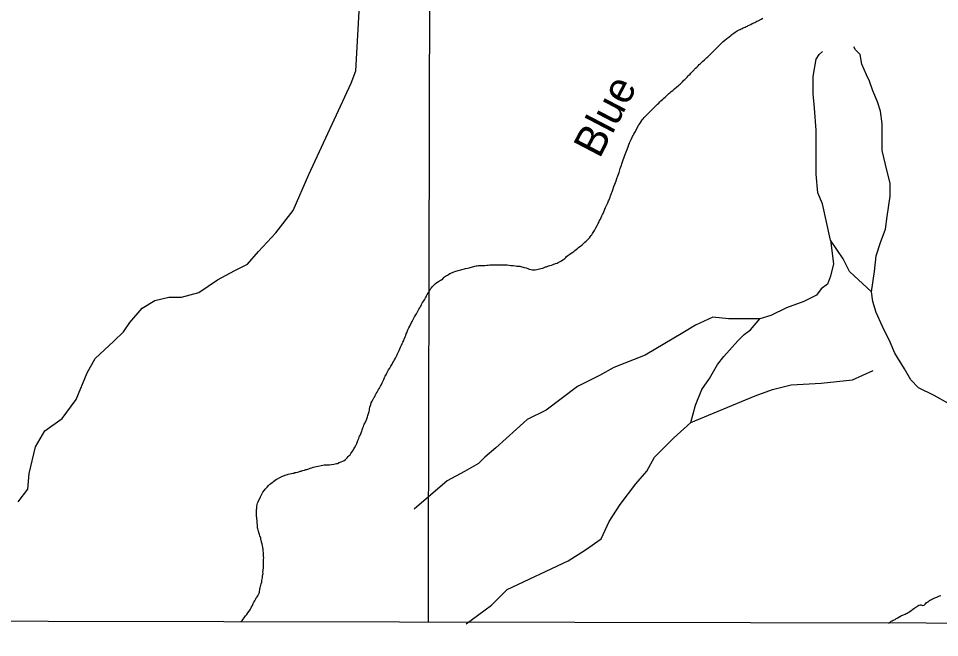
# Model space of a CAD drawing. Extents: x 3192927 to 3230760, y 831141 to 856475.
# Drawn here: x 3201003 to 3203997, y 836487 to 838498 of the extents above; entities that cross this region are included whole.
import ezdxf

# ---------------------------------------------------------------- set-up
doc = ezdxf.new("R2010")
doc.units = 0
for name, color, linetype in [('V-GRID-FRAM', 7, 'Continuous'), ('V-GRID-MAJR', 7, 'Continuous'), ('V-RIVR-IDEN', 7, 'Continuous'), ('V-TOPO-SHOR', 7, 'Continuous')]:
    doc.layers.add(name, color=color, linetype=linetype)

msp = doc.modelspace()

# ---------------------------------------------------------------- linework, layer by layer
at = {"layer": 'V-GRID-FRAM'}
msp.add_lwpolyline([(3197144.3, 854733.3), (3228527.7, 854674), (3228501.2, 836486.7), (3197102, 836546.1), (3197144.3, 854733.3)], dxfattribs=at)
at = {"layer": 'V-GRID-MAJR'}
msp.add_spline([(3202335.2, 836536.2), (3202348.4, 842596.7), (3202361.7, 848659.1), (3202374.9, 854721.5), (3202374.9, 854723.4)], degree=3, dxfattribs=at)
at = {"layer": 'V-TOPO-SHOR'}
for points in [[(3201002.3, 836928.1), (3201032.9, 836969), (3201038, 837020), (3201058.3, 837106.9), (3201088.9, 837158), (3201145.1, 837198.9), (3201191, 837260.2), (3201226.7, 837347.1), (3201252.2, 837393), (3201313.4, 837449.3), (3201344, 837479.9), (3201364.4, 837510.6), (3201405.3, 837556.6), (3201446.1, 837582.2), (3201492.1, 837592.4), (3201532.9, 837592.5), (3201589.1, 837607.8), (3201650.3, 837648.7), (3201706.5, 837679.4), (3201747.3, 837699.9), (3201783, 837740.8), (3201839.2, 837802.1), (3201895.3, 837873.7), (3201946.3, 837991.2), (3202083.9, 838287.5), (3202099.2, 838328.4), (3202139.5, 839043.4)], [(3203135.6, 838269.3), (3203143.1, 838275.5), (3203147.1, 838279.5), (3203150.2, 838282.1), (3203153.1, 838284.7), (3203158.4, 838289.3), (3203161.2, 838292.1), (3203165.8, 838297.4), (3203168.7, 838300), (3203175.9, 838307.8), (3203179.2, 838311.2), (3203181.6, 838313.5), (3203185.7, 838317.6), (3203188.3, 838320.2), (3203194.3, 838326.4), (3203203.9, 838336.4), (3203207.5, 838340), (3203212.3, 838344.7), (3203215.6, 838348.3), (3203218.7, 838351.1), (3203225.7, 838357.8), (3203232.6, 838364), (3203236, 838366.8), (3203240.5, 838371.1), (3203243.4, 838373.8), (3203247.5, 838377.8), (3203252.5, 838382.6), (3203258.5, 838388.7), (3203262.1, 838392.3), (3203266.4, 838396.4), (3203268.5, 838398.7), (3203271.7, 838401.8), (3203279.6, 838409.2), (3203285.1, 838414.9), (3203287.9, 838418), (3203293.4, 838423), (3203297.3, 838426.6), (3203305.7, 838433.2), (3203311.4, 838437.8), (3203318.8, 838443.5), (3203321.2, 838445.6), (3203327.9, 838450.1), (3203332.2, 838453.7), (3203338.9, 838457.5), (3203345.6, 838461.1), (3203348.7, 838462.5), (3203352.1, 838464.1), (3203355.2, 838465.6), (3203358.8, 838467.5), (3203364.3, 838469.8), (3203367.8, 838471.7), (3203371.9, 838473.4), (3203375, 838474.8), (3203380.3, 838477.2), (3203383.6, 838478.8), (3203387.9, 838481.2), (3203395.8, 838484.8), (3203399.9, 838487.2), (3203403.2, 838488.8), (3203406.8, 838490.7), (3203416.4, 838495.7), (3203422.1, 838498.8)], [(3204025.5, 837247.2), (3203979.5, 837272.7), (3203928.4, 837298.2), (3203902.9, 837323.7), (3203882.4, 837359.5), (3203851.7, 837410.5), (3203836.4, 837446.2), (3203810.8, 837497.3), (3203790.3, 837543.2), (3203780.1, 837579), (3203775, 837609.6), (3203785.1, 837676), (3203790.2, 837727.1), (3203805.5, 837773.1), (3203820.8, 837813.9), (3203825.8, 837854.8), (3203836, 837921.2), (3203836, 837962.1), (3203820.6, 838023.3), (3203810.3, 838069.3), (3203810.3, 838120.4), (3203810.3, 838156.1), (3203805.1, 838197), (3203794.9, 838227.6), (3203779.5, 838263.3), (3203769.3, 838294), (3203759.1, 838314.4), (3203743.7, 838350.1), (3203738.6, 838380.8), (3203723.2, 838396.1), (3203718.1, 838406.3)], [(3203775, 837609.6), (3203703.4, 837676), (3203682.9, 837716.8), (3203662.5, 837747.4), (3203642, 837778), (3203616.4, 837895.5), (3203601, 837931.2), (3203595.9, 837992.5), (3203595.8, 838079.3), (3203595.8, 838135.5), (3203590.6, 838207), (3203585.5, 838253), (3203585.4, 838309.2), (3203595.6, 838365.3), (3203605.8, 838380.7), (3203616, 838390.9)], [(3202834.7, 837762.9), (3202837.1, 837764.8), (3202840.6, 837768.3), (3202843.3, 837771), (3202848.1, 837775), (3202852.4, 837779), (3202855, 837781.2), (3202858.8, 837785.5), (3202861, 837788.3), (3202864.4, 837792.6), (3202866, 837795.5), (3202868.2, 837799.3), (3202874.9, 837809.5), (3202877.3, 837813.6), (3202880, 837817.6), (3202883.6, 837825), (3202885.2, 837828.1), (3202886.7, 837831.7), (3202889.8, 837837.4), (3202891.5, 837841.2), (3202894.1, 837846.2), (3202897, 837851.7), (3202899.4, 837856.7), (3202901.3, 837861), (3202903, 837864.1), (3202905.2, 837869.8), (3202911.4, 837883.4), (3202914.1, 837890.1), (3202916, 837894.4), (3202918.7, 837899.6), (3202920.8, 837905.1), (3202922.3, 837908.9), (3202925.6, 837918), (3202926.8, 837921.3), (3202929, 837926.8), (3202930.9, 837930.6), (3202932.1, 837934.7), (3202934.3, 837940.9), (3202938.2, 837952.3), (3202940.8, 837960), (3202943, 837965.2), (3202945.1, 837970.2), (3202948, 837978.3), (3202951.2, 837986.9), (3202953.1, 837992.7), (3202955.2, 837997.9), (3202956.2, 838001.5), (3202957.7, 838006.5), (3202958.9, 838010.1), (3202962.7, 838021.5), (3202963.9, 838025.6), (3202966.3, 838032), (3202968.7, 838038.9), (3202970.4, 838043.7), (3202972.8, 838050.8), (3202977.9, 838064.4), (3202980.8, 838072.5), (3202982.2, 838076.1), (3202984.2, 838081.1), (3202986.8, 838088.8), (3202988.5, 838092.3), (3202990.4, 838096.6), (3202991.9, 838100.2), (3202994.5, 838105), (3202999.1, 838114.3), (3203001, 838118.1), (3203003.1, 838121.7), (3203006.3, 838127.4), (3203007.9, 838131.2), (3203011.8, 838138.1), (3203016.1, 838146.2), (3203018.5, 838151), (3203020.4, 838154.1), (3203023.3, 838158.4), (3203026.4, 838163.1), (3203030.5, 838168.6), (3203033.6, 838172.2), (3203037, 838176.2), (3203039.4, 838179.1), (3203042.2, 838181.9), (3203049.7, 838189.8), (3203052.5, 838192.4), (3203056.6, 838196.5), (3203059, 838198.8), (3203062.4, 838202.2), (3203064.8, 838204.6), (3203071.7, 838211), (3203076.3, 838216), (3203079.8, 838219.6), (3203083.7, 838223.4), (3203087.5, 838227.2), (3203091.1, 838230.5), (3203096.8, 838236), (3203100.7, 838239.3), (3203104.5, 838242.9), (3203109.8, 838247.6), (3203117, 838254.1), (3203119.8, 838256.7), (3203124.6, 838260.7), (3203129.6, 838264.5), (3203135.6, 838269.3)], [(3203642, 837778), (3203652.3, 837701.4), (3203642.1, 837660.6), (3203631.9, 837635), (3203611.5, 837619.7), (3203596.2, 837599.3), (3203555.4, 837578.8), (3203499.2, 837558.3), (3203448.2, 837532.7), (3203412.4, 837522.5), (3203366.5, 837522.5), (3203310.3, 837522.4), (3203259.2, 837527.5), (3203203, 837501.9), (3203162.2, 837476.3), (3203039.7, 837404.7), (3202937.6, 837363.8), (3202891.6, 837338.2), (3202820.2, 837302.4), (3202718.1, 837225.7), (3202656.8, 837195), (3202621.1, 837164.3), (3202554.8, 837103), (3202519, 837072.3), (3202498.6, 837051.9), (3202452.7, 837026.3), (3202396.5, 836995.6), (3202289.3, 836903.6)], [(3202352.2, 837630.9), (3202356.3, 837634.5), (3202358.7, 837636.6), (3202362.8, 837639.9), (3202368.5, 837643.5), (3202371.1, 837645.2), (3202374.5, 837647.5), (3202377.6, 837649.4), (3202382.4, 837652.3), (3202385.2, 837656.1), (3202387.6, 837658.5), (3202390.7, 837660.6), (3202397.2, 837664.4), (3202400.3, 837666.3), (3202405.1, 837669.2), (3202413.2, 837672.5), (3202416.3, 837673.7), (3202421.1, 837675.6), (3202424.5, 837676.8), (3202429.2, 837678.4), (3202432.1, 837679.4), (3202436.6, 837680.3), (3202440.7, 837681.2), (3202443.8, 837682), (3202448.4, 837683.4), (3202452.7, 837684.8), (3202455.8, 837685.5), (3202463.2, 837686.9), (3202468.2, 837688.1), (3202471.1, 837689), (3202475.8, 837690.2), (3202486.1, 837692.8), (3202490.2, 837694.2), (3202494.2, 837694.9), (3202498.3, 837695.1), (3202503.5, 837695.6), (3202508.8, 837695.6), (3202516, 837696), (3202519.1, 837695.6), (3202524.8, 837696.5), (3202529.1, 837697), (3202534.8, 837697.7), (3202541.3, 837697.6), (3202544.4, 837697.9), (3202549.6, 837697.6), (3202559.2, 837697.8), (3202567.5, 837698), (3202574, 837697.8), (3202582.3, 837698), (3202591.2, 837697.5), (3202597.9, 837696.8), (3202603.3, 837695.8), (3202610.7, 837695), (3202618.1, 837694.3), (3202622.2, 837693.8), (3202629.1, 837693.1), (3202632.5, 837692.8), (3202638.9, 837691.4), (3202643.7, 837690.4), (3202647, 837689.4), (3202653.2, 837687.5), (3202658.5, 837685.6), (3202663, 837683.9), (3202669.4, 837682.2), (3202673.5, 837681.7), (3202677.1, 837681.5), (3202682.6, 837681.9), (3202687.3, 837682.9), (3202691.6, 837684), (3202696.4, 837684.5), (3202700.2, 837685.5), (3202706.7, 837687.3), (3202709.6, 837688.3), (3202715.5, 837690.7), (3202718.6, 837691.6), (3202723, 837693), (3202730.4, 837695.4), (3202735.1, 837696.3), (3202740.6, 837698.5), (3202748.8, 837701.8), (3202753.3, 837703.2), (3202756.9, 837704.9), (3202763.8, 837708.2), (3202767.6, 837710.3), (3202772.2, 837713.4), (3202775.8, 837716.3), (3202778.2, 837718.4), (3202781.5, 837722), (3202783.9, 837724.3), (3202788, 837727.7), (3202792.1, 837730.3), (3202794.5, 837732.2), (3202799.7, 837735.8), (3202804.3, 837738.8), (3202807.6, 837741), (3202811.7, 837744.3), (3202815.8, 837747.4), (3202821, 837752.2), (3202824.6, 837754.8), (3202830.1, 837758.8), (3202834.7, 837762.9)], [(3202118.7, 837157), (3202120.4, 837162), (3202122.1, 837167.7), (3202124.2, 837172.7), (3202125.7, 837176.5), (3202126.9, 837180.4), (3202129.3, 837184.9), (3202132.6, 837192), (3202134.8, 837197.1), (3202137, 837203.5), (3202138.7, 837207.8), (3202141.1, 837214.5), (3202142.5, 837220.9), (3202143.7, 837225.9), (3202144.2, 837229.3), (3202145.4, 837235), (3202147.8, 837244), (3202149.8, 837248.8), (3202152.6, 837254.3), (3202154.8, 837258.6), (3202158.2, 837265.3), (3202159.8, 837268.1), (3202162.3, 837272.7), (3202165.9, 837279.6), (3202168.5, 837284.3), (3202173.5, 837292.2), (3202176.2, 837296.7), (3202177.9, 837299.6), (3202180, 837303.4), (3202181.5, 837306.3), (3202185.3, 837314.4), (3202187.2, 837318.2), (3202189.1, 837322.7), (3202190.6, 837325.6), (3202193, 837332), (3202195.2, 837335.8), (3202199, 837342.7), (3202200.4, 837346.1), (3202202.4, 837349.6), (3202206, 837356.1), (3202209.8, 837362.5), (3202213.2, 837368), (3202215.6, 837372), (3202217.2, 837375.1), (3202220.1, 837379.9), (3202222.5, 837384.4), (3202225.4, 837389.2), (3202228.5, 837394.7), (3202231.4, 837400.9), (3202233.6, 837405.4), (3202234.8, 837408.8), (3202236.7, 837413.3), (3202239.8, 837419.7), (3202242.5, 837425), (3202244.4, 837429.7), (3202245.8, 837432.8), (3202248, 837437.1), (3202250.4, 837442.1), (3202252.6, 837446.9), (3202255, 837452.1), (3202256.2, 837456.2), (3202259.3, 837463.3), (3202261.5, 837468.4), (3202263.4, 837473.4), (3202264.8, 837476.7), (3202267.5, 837483.4), (3202268.9, 837486.2), (3202270.6, 837490.3), (3202272, 837493.2), (3202274.9, 837498.6), (3202280.7, 837510.1), (3202282.9, 837513.9), (3202284.5, 837517.7), (3202287.2, 837522.5), (3202290.3, 837528.4), (3202292.5, 837532.2), (3202294.1, 837534.9), (3202296.1, 837538.7), (3202299.4, 837544.9), (3202304.5, 837553.5), (3202307.1, 837557.7), (3202308.8, 837561.1), (3202310.5, 837563.9), (3202312.9, 837568.5), (3202314.3, 837571.3), (3202316.2, 837574.9), (3202320.1, 837580.6), (3202322.2, 837584.4), (3202325.6, 837590.2), (3202327.8, 837594.2), (3202329.2, 837597.1), (3202331.6, 837601.6), (3202334.2, 837605.4), (3202336.4, 837609), (3202337.8, 837611.8), (3202340.7, 837616.1), (3202343.1, 837620.7), (3202345, 837623.3), (3202347.2, 837625.7), (3202349.8, 837628.5), (3202352.2, 837630.9)], [(3202458.2, 836530.9), (3202539.9, 836592.3), (3202590.9, 836643.4), (3202790, 836735.5), (3202846.1, 836771.3), (3202897.2, 836807.1), (3202922.7, 836863.3), (3202958.4, 836919.5), (3203009.4, 836985.9), (3203045.1, 837026.8), (3203070.6, 837072.8), (3203131.8, 837134.1), (3203188, 837185.2), (3203203.3, 837241.4), (3203223.6, 837292.5), (3203249.1, 837328.3), (3203274.6, 837374.3), (3203295.1, 837399.8), (3203341, 837450.9), (3203361.4, 837471.4), (3203381.8, 837486.7), (3203412.4, 837522.5)], [(3203188, 837185.2), (3203397.3, 837272.2), (3203453.5, 837292.7), (3203514.7, 837308.1), (3203611.8, 837313.3), (3203713.9, 837323.6), (3203780.3, 837354.3)], [(3201780.1, 836843.4), (3201779.4, 836853.2), (3201779, 836858.7), (3201778.7, 836862.7), (3201778.3, 836867.2), (3201777.6, 836872), (3201777.4, 836877.3), (3201776.9, 836880.4), (3201776.7, 836888.5), (3201776.7, 836893.3), (3201776.9, 836899.2), (3201777, 836902.6), (3201777.4, 836905.9), (3201778.2, 836912.6), (3201778.9, 836919.3), (3201779.9, 836923.8), (3201781.6, 836928.1), (3201783.5, 836931.5), (3201787.1, 836938.6), (3201789.3, 836943.6), (3201792.4, 836950.3), (3201794.5, 836954.3), (3201797.4, 836959.1), (3201802.2, 836965.3), (3201805.1, 836968.6), (3201808, 836972), (3201811.3, 836975.8), (3201815.9, 836980.8), (3201819.5, 836984.8), (3201822.8, 836987.4), (3201827.1, 836990.5), (3201830.7, 836992.7), (3201833.1, 836994.8), (3201837.4, 836997.7), (3201841.2, 837001), (3201845.3, 837002.9), (3201852, 837006.5), (3201855.4, 837008.3), (3201858.2, 837009.5), (3201864, 837011.7), (3201867.1, 837012.9), (3201870.2, 837014), (3201873.5, 837015.5), (3201876.9, 837016.6), (3201880, 837017.3), (3201884.5, 837018.5), (3201890.2, 837019.9), (3201894.8, 837021.1), (3201897.9, 837021.3), (3201901.5, 837022.5), (3201906, 837023.5), (3201913.9, 837025.6), (3201918, 837027), (3201921.3, 837027.7), (3201926.3, 837029.4), (3201932.1, 837031), (3201936.8, 837032.4), (3201939.9, 837033.2), (3201946.4, 837035.3), (3201950.9, 837036.7), (3201956, 837038.4), (3201960.7, 837039.8), (3201966.5, 837041.2), (3201971, 837042.1), (3201976.5, 837043.3), (3201986.8, 837045.9), (3201992, 837046.8), (3201996.8, 837047.5), (3202003, 837048.2), (3202006.4, 837048.2), (3202013.8, 837048.2), (3202020, 837049.1), (3202028.3, 837050.1), (3202032.2, 837051), (3202036.5, 837052.2), (3202039.8, 837052.7), (3202045.8, 837055), (3202051.5, 837057.4), (3202057.5, 837060), (3202061.8, 837062.4), (3202065.6, 837064.8), (3202068.3, 837066.9), (3202071.1, 837070.5), (3202074.5, 837074.5), (3202078.1, 837078.6), (3202080.7, 837080.9), (3202083.6, 837084.5), (3202089.1, 837092.6), (3202091.5, 837096.9), (3202093.2, 837100), (3202094.9, 837102.9), (3202099.4, 837111), (3202102.3, 837117.4), (3202105, 837124.1), (3202106.2, 837126.9), (3202109.1, 837133.9), (3202110.5, 837137.9), (3202111.7, 837140.8), (3202114.1, 837145.5), (3202116.5, 837151.7), (3202118.7, 837157)], [(3201726.3, 836537.4), (3201727.1, 836538.7), (3201729.5, 836541.7), (3201733.6, 836546.5), (3201736.5, 836550.8), (3201738.6, 836554.4), (3201741, 836557.5), (3201745.1, 836562.2), (3201748.5, 836567), (3201752.5, 836572.2), (3201756.8, 836579.1), (3201759.2, 836583.7), (3201760.7, 836586.5), (3201763.1, 836590.6), (3201764.8, 836593.7), (3201766.2, 836597.3), (3201768.4, 836601.6), (3201771, 836606.3), (3201772.9, 836610.1), (3201774.1, 836613), (3201775.8, 836615.6), (3201778.7, 836619.4), (3201780.9, 836622.8), (3201783.5, 836626.8), (3201784.9, 836631.1), (3201785.9, 836634.4), (3201787.9, 836644.7), (3201788.3, 836648.3), (3201789.5, 836652.6), (3201790.5, 836657.3), (3201791.7, 836661.2), (3201793.4, 836666.7), (3201794.4, 836672.1), (3201794.9, 836676.9), (3201795.6, 836680.7), (3201796.3, 836686.7), (3201797.1, 836691.9), (3201797.8, 836695), (3201797.3, 836698.9), (3201797.8, 836704.6), (3201799, 836714.1), (3201799.3, 836718.7), (3201799.3, 836723.9), (3201799.3, 836729.4), (3201799.3, 836732.5), (3201799.6, 836737.1), (3201799.8, 836741.6), (3201799.9, 836745.9), (3201799.2, 836751.4), (3201799.2, 836759), (3201799.2, 836763.6), (3201798.7, 836767.1), (3201798.3, 836773.4), (3201797.6, 836777.7), (3201796.9, 836780.8), (3201795.9, 836784.6), (3201794.5, 836790.6), (3201793.1, 836796.3), (3201792.9, 836799.6), (3201791.2, 836803.9), (3201790.3, 836809.7), (3201787.9, 836817.6), (3201786.7, 836821.6), (3201785.1, 836825.2), (3201783.9, 836828.3), (3201782.7, 836833.1), (3201781.8, 836836), (3201780.6, 836839.8), (3201780.1, 836843.4)], [(3203830.9, 836533.4), (3203833.6, 836535.2), (3203836.7, 836537.8), (3203839.8, 836539.7), (3203843.1, 836541.4), (3203846, 836543), (3203849.1, 836544.4), (3203852, 836545.9), (3203855.6, 836548.2), (3203858.9, 836550.1), (3203862.5, 836552), (3203867.1, 836554.7), (3203869.7, 836556.3), (3203873.3, 836558.5), (3203876.1, 836559.4), (3203879.3, 836560.6), (3203884.3, 836563), (3203888.1, 836564.6), (3203891.7, 836566.5), (3203894.6, 836567.9), (3203897.2, 836569.6), (3203900.5, 836571.5), (3203903.9, 836574.4), (3203906.3, 836576.3), (3203908.7, 836578.2), (3203913.2, 836581.2), (3203916.1, 836583.2), (3203919.7, 836585.5), (3203923.5, 836587.9), (3203926.4, 836589.3), (3203929.7, 836591.5), (3203933.1, 836593.1), (3203936.4, 836593.4), (3203939.5, 836592.2), (3203942.6, 836591.4), (3203946.4, 836592.1), (3203949.1, 836593.8), (3203951, 836596.6), (3203952.9, 836599.3), (3203956, 836601.4), (3203958.7, 836603.3), (3203961.5, 836605.5), (3203964.2, 836607.1), (3203969.9, 836610.2), (3203974, 836612.1), (3203976.8, 836613.3), (3203981.6, 836615.7), (3203985, 836617.1), (3203988.3, 836618.5), (3203992.4, 836620.4), (3203996.4, 836622.1), (3204000.3, 836623.7)]]:
    msp.add_lwpolyline(points, dxfattribs=at)

# ---------------------------------------------------------------- texts
at = {"layer": 'V-RIVR-IDEN'}
msp.add_text('Blue', height=100, rotation=62.4429, dxfattribs=at).set_placement((3202891.3, 838040.2))

doc.saveas('drawing.dxf')
